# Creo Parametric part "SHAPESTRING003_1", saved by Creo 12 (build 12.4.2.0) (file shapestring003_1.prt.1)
Units: Custom; MM, KILOGRAM, SECS

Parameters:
  PTC_WM_ITERATION = "0"
  PTC_WM_VERSION = "-.0"
  PTC_WM_LIFECYCLE_STATE = "In Work"
  PTC_WM_LIFECYCLE = "MO_CADDocument"
  PTC_WM_CREATED_BY = "Maximilian Roepper (Z0017RMS: MO)"
  PTC_WM_CREATED_ON = "18-Sep-26 11:36:42 AM"
  PTC_WM_MODIFIED_BY = "Maximilian Roepper (Z0017RMS: MO)"
  PTC_WM_MODIFIED_ON = "18-Sep-26 11:36:46 AM"
  PDMLINKNUMBER = "PDM000071454950"
  PTC_WM_NAME = "shapestring003_1.prt"
  PTC_WM_NUMBER = "PDM000071454950"

Other parameters: WEIGHT, WEIGHT_FACTOR, WEIGHT_ADD, _MASS_TEMP, _DIFF_TEMP, MC_ERRORS, SUPPLIER

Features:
  1. coordinate system
  2. datum plane "PRT_YZ"
  3. datum plane "PRT_XY"
  4. datum plane "PRT_XZ"
  5. coordinate system
  6. datum axis
  7. datum axis
  8. datum axis
  9. coordinate system
  10. imported feature
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
Other named items: PRT, SIEMENS_MO, DRW_VIEW_ORG, PRT_X, PRT_Y, PRT_Z, CS0, ROUGH_GROB

Layers: 00_STD_CSYS-KSYS, 01_STD_PLANES-EBENEN, 02_STD_AXES-ACHSEN, 03_STD_CSYS-KSYS, 24_IMPORT_FEAT-IMPORT_KE, WHITE

Surfaces: 1 plane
